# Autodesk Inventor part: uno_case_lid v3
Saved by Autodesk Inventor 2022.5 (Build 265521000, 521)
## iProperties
Created: 2024-05
Part Number: uno_case_lid v3
Material: Generic
Document SubType Name: Modeling
Designer: AdminForWorker
Density: 1 g/cm^3
Appearance: Default
Title: uno_case_lid v3
Author: AdminForWorker
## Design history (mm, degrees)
feature "MeshBody1"
body "Solid1"
